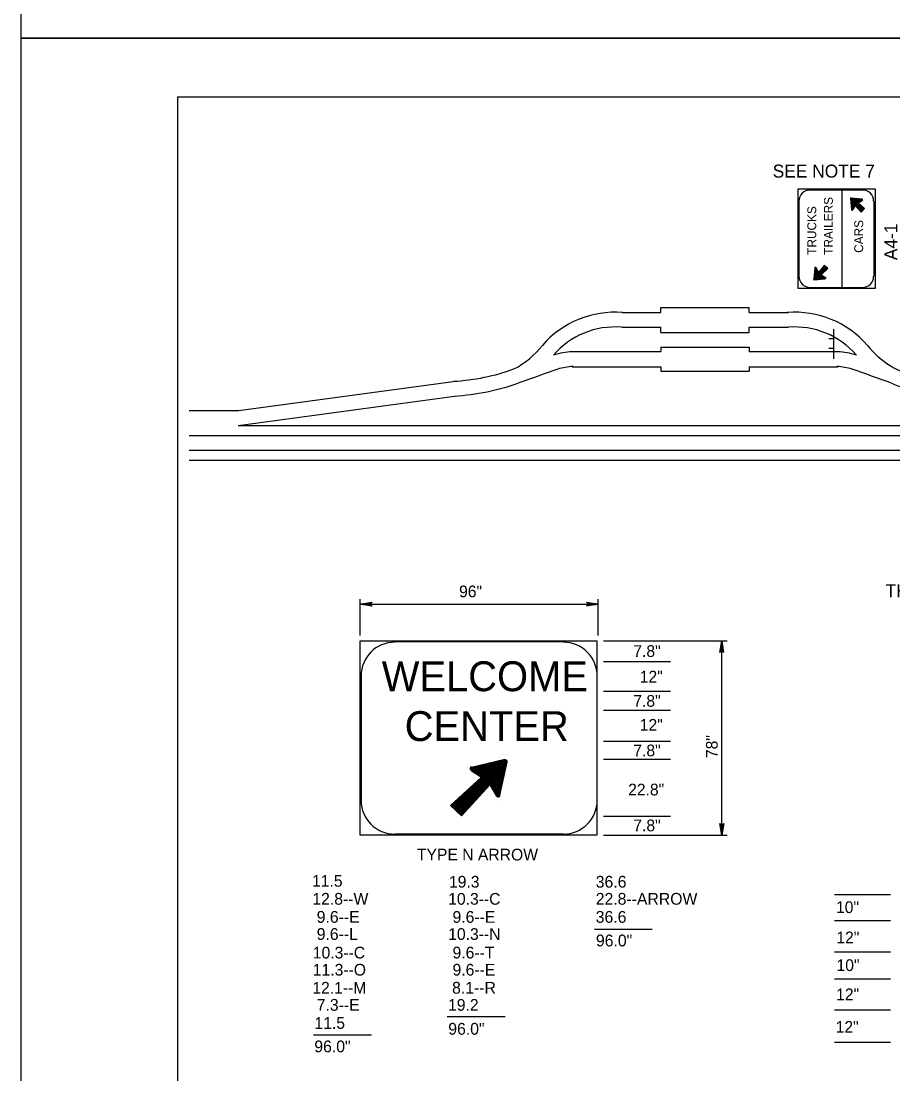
# Model space of a CAD drawing. Extents: x 2189973 to 2192941, y 2147557 to 2151454.
# Drawn here: x 2189973 to 2190705, y 2148636 to 2149520 of the extents above; entities that cross this region are included whole.
import ezdxf

# ---------------------------------------------------------------- set-up
doc = ezdxf.new("R2010")
doc.units = 0
doc.layers.add('Default', color=7, linetype='Continuous')
doc.layers.add('PLT-BNDY', color=7, linetype='Continuous')

# ---------------------------------------------------------------- blocks, each defined once
blk = doc.blocks.new('RARROW')
at = {"layer": 'Default'}
blk.add_lwpolyline([(-18.156, 2.28), (-17.479, 0.966), (0, 0), (-18.156, 2.28), (-19.086, 3.077), (0, 0), (-17.465, -0.864), (-18.103, -2.164), (0, 0), (-19.086, -3.033), (-18.103, -2.164)], dxfattribs=at)

msp = doc.modelspace()

# ---------------------------------------------------------------- linework, layer by layer
at = {"layer": 'Default'}
for p, q in [((2190104.48, 2149456.38), (2192683.21, 2149456.38)), ((2190104.48, 2149456.38), (2190104.48, 2147605.99)), ((2190635.15, 2149378.46), (2190679.45, 2149378.46)), ((2190662.22, 2149296.44), (2190662.22, 2149378.46)), ((2190669.19, 2149371.08), (2190670.01, 2149362.06)), ((2190679.04, 2149370.67), (2190669.6, 2149371.49)), ((2190669.6, 2149371.08), (2190669.6, 2149371.08)), ((2190675.76, 2149367.39), (2190679.04, 2149369.44)), ((2190679.04, 2149369.85), (2190679.04, 2149369.85)), ((2190679.86, 2149369.85), (2190679.86, 2149369.85)), ((2190679.86, 2149369.85), (2190679.86, 2149369.85)), ((2190670.42, 2149362.06), (2190670.42, 2149362.06)), ((2190670.42, 2149360.83), (2190670.42, 2149360.83)), ((2190670.42, 2149360.83), (2190670.42, 2149360.83)), ((2190673.29, 2149365.34), (2190671.24, 2149362.06)), ((2190673.29, 2149365.34), (2190673.29, 2149365.34)), ((2190673.29, 2149365.34), (2190678.22, 2149359.6)), ((2190674.52, 2149366.57), (2190674.52, 2149366.57)), ((2190675.76, 2149367.39), (2190675.76, 2149367.39)), ((2190681.09, 2149362.88), (2190675.76, 2149367.39)), ((2190678.22, 2149359.6), (2190681.09, 2149362.88)), ((2190681.09, 2149362.88), (2190681.09, 2149362.88)), ((2190678.22, 2149359.6), (2190678.22, 2149359.6)), ((2190639.26, 2149312.85), (2190638.44, 2149303.82)), ((2190640.08, 2149313.67), (2190640.08, 2149313.67)), ((2190640.08, 2149313.67), (2190640.08, 2149313.67)), ((2190640.08, 2149312.85), (2190640.08, 2149312.85)), ((2190642.54, 2149309.16), (2190640.49, 2149313.26)), ((2190647.05, 2149314.9), (2190642.54, 2149309.16)), ((2190642.54, 2149309.16), (2190642.54, 2149309.16)), ((2190643.36, 2149308.33), (2190643.36, 2149308.33)), ((2190644.59, 2149307.1), (2190650.33, 2149312.44)), ((2190644.59, 2149307.1), (2190644.59, 2149307.1)), ((2190644.59, 2149307.1), (2190647.87, 2149305.05)), ((2190647.05, 2149314.9), (2190647.05, 2149314.9)), ((2190650.33, 2149312.44), (2190647.05, 2149314.9)), ((2190650.33, 2149312.44), (2190650.33, 2149312.44)), ((2190638.44, 2149303.41), (2190638.44, 2149303.41)), ((2190638.44, 2149303.41), (2190638.44, 2149303.41)), ((2190638.85, 2149303.82), (2190638.85, 2149303.82)), ((2190638.85, 2149303), (2190647.87, 2149303.82)), ((2190647.87, 2149304.64), (2190647.87, 2149304.64)), ((2190648.69, 2149304.64), (2190648.69, 2149304.64)), ((2190648.69, 2149304.64), (2190648.69, 2149304.64)), ((2190633.92, 2149295.62), (2190627.77, 2149295.62)), ((2190635.15, 2149296.44), (2190679.45, 2149296.44)), ((2190663.86, 2149295.62), (2190659.35, 2149295.62)), ((2190477.26, 2149275.53), (2190510.07, 2149275.53)), ((2190510.07, 2149279.63), (2190584.3, 2149279.63)), ((2190510.07, 2149275.53), (2190510.07, 2149279.63)), ((2190584.3, 2149275.53), (2190584.3, 2149279.63)), ((2190584.3, 2149275.53), (2190617.11, 2149275.53)), ((2190477.26, 2149263.22), (2190510.07, 2149263.22)), ((2190510.07, 2149258.71), (2190510.07, 2149263.22)), ((2190584.3, 2149258.71), (2190584.3, 2149263.22)), ((2190584.3, 2149263.22), (2190617.11, 2149263.22)), ((2190510.07, 2149258.71), (2190584.3, 2149258.71)), ((2190655.25, 2149236.57), (2190655.25, 2149261.58)), ((2190510.07, 2149246.41), (2190584.3, 2149246.41)), ((2190510.07, 2149246.41), (2190510.07, 2149242.72)), ((2190584.3, 2149246.41), (2190584.3, 2149242.72)), ((2190655.25, 2149253.38), (2190651.15, 2149253.38)), ((2190655.25, 2149245.18), (2190651.15, 2149245.18)), ((2190435.84, 2149242.72), (2190510.07, 2149242.72)), ((2190584.3, 2149242.72), (2190658.53, 2149242.72)), ((2190435.84, 2149230.01), (2190510.07, 2149230.01)), ((2190510.07, 2149230.01), (2190510.07, 2149226.31)), ((2190584.3, 2149230.01), (2190584.3, 2149226.31)), ((2190584.3, 2149230.01), (2190658.53, 2149230.01)), ((2190510.07, 2149226.31), (2190584.3, 2149226.31)), ((2190153.69, 2149193.1), (2190335.78, 2149217.7)), ((2190155.33, 2149180.79), (2190337.01, 2149205.4)), ((2190337.01, 2149205.4), (2190337.01, 2149205.4)), ((2190337.01, 2149205.4), (2190337.01, 2149205.4)), ((2190155.33, 2149193.1), (2190114.32, 2149193.1)), ((2190155.33, 2149180.79), (2190939.04, 2149180.79)), ((2190155.33, 2149180.79), (2190155.33, 2149180.79)), ((2190155.33, 2149180.79), (2190155.33, 2149180.79)), ((2190114.32, 2149172.18), (2192679.93, 2149172.18)), ((2190114.32, 2149159.88), (2192679.93, 2149159.88)), ((2190114.32, 2149151.68), (2192679.93, 2149151.68)), ((2190257.86, 2149004.45), (2190257.86, 2149034.8)), ((2190457.58, 2149004.45), (2190457.58, 2149034.8)), ((2190257.86, 2149030.69), (2190457.58, 2149030.69)), ((2190462.09, 2148999.94), (2190565.73, 2148999.94)), ((2190561.21, 2148836.72), (2190561.21, 2148999.94)), ((2190462.09, 2148982.71), (2190518.12, 2148982.71)), ((2190258.68, 2148970.82), (2190258.68, 2148865.83)), ((2190456.76, 2148865.83), (2190456.76, 2148970.82)), ((2190462.09, 2148957.7), (2190518.12, 2148957.7)), ((2190462.09, 2148941.7), (2190518.12, 2148941.7)), ((2190462.09, 2148915.87), (2190518.12, 2148915.87)), ((2190379.25, 2148900.28), (2190351.36, 2148893.72)), ((2190381.3, 2148900.69), (2190381.3, 2148900.69)), ((2190462.09, 2148900.69), (2190518.12, 2148900.69)), ((2190348.08, 2148893.31), (2190348.08, 2148893.31)), ((2190375.15, 2148870.34), (2190380.89, 2148897.82)), ((2190359.56, 2148885.52), (2190333.73, 2148861.73)), ((2190350.95, 2148891.26), (2190359.56, 2148885.52)), ((2190359.56, 2148885.52), (2190359.56, 2148885.52)), ((2190342.75, 2148853.12), (2190366.54, 2148878.96)), ((2190366.54, 2148878.96), (2190366.54, 2148878.96)), ((2190366.54, 2148878.96), (2190372.28, 2148869.52)), ((2190374.33, 2148866.24), (2190374.33, 2148866.24)), ((2190333.73, 2148861.73), (2190342.75, 2148853.12)), ((2190462.09, 2148852.71), (2190518.12, 2148852.71)), ((2190462.09, 2148836.72), (2190565.73, 2148836.72)), ((2190702.84, 2148786.67), (2190655.73, 2148786.67)), ((2190702.84, 2148764.93), (2190655.73, 2148764.93)), ((2190454.45, 2148758.02), (2190502.75, 2148758.02)), ((2190702.84, 2148738.69), (2190655.73, 2148738.69)), ((2190702.84, 2148716.13), (2190655.73, 2148716.13)), ((2190702.84, 2148689.88), (2190655.73, 2148689.88)), ((2190330.71, 2148684.65), (2190379.54, 2148684.65)), ((2190218.72, 2148669.39), (2190267.19, 2148669.39)), ((2190702.84, 2148662.82), (2190655.73, 2148662.82))]:
    msp.add_line(p, q, dxfattribs=at)
for points in [[(2190625.31, 2149295.62), (2190625.31, 2149379.28), (2190631.05, 2149379.28), (2190638.44, 2149379.28), (2190643.77, 2149379.28), (2190651.56, 2149379.28), (2190656.89, 2149379.28), (2190663.04, 2149379.28), (2190675.34, 2149379.28), (2190690.11, 2149379.28), (2190690.11, 2149295.62), (2190672.47, 2149295.62), (2190665.5, 2149295.62), (2190656.89, 2149295.62), (2190647.46, 2149295.62), (2190635.15, 2149295.62), (2190625.31, 2149295.62)], [(2190626.13, 2149305.87), (2190626.13, 2149369.03)], [(2190669.19, 2149371.08), (2190670.42, 2149362.47), (2190670.42, 2149362.06), (2190670.83, 2149361.65), (2190670.83, 2149362.06), (2190673.29, 2149365.75), (2190673.29, 2149365.75), (2190678.22, 2149360.01), (2190680.68, 2149362.88), (2190675.34, 2149367.39), (2190675.34, 2149367.39), (2190679.04, 2149369.85), (2190679.45, 2149369.85), (2190679.04, 2149370.26), (2190679.04, 2149370.26), (2190669.6, 2149371.49), (2190669.6, 2149371.49), (2190669.19, 2149371.08), (2190669.6, 2149371.08), (2190670.42, 2149362.06), (2190672.88, 2149365.75), (2190678.22, 2149360.42), (2190680.68, 2149362.88), (2190674.93, 2149367.39), (2190679.04, 2149370.26), (2190669.6, 2149371.08), (2190670.42, 2149362.47), (2190672.88, 2149366.16), (2190678.22, 2149360.42), (2190680.27, 2149362.88), (2190674.93, 2149367.39), (2190679.04, 2149369.85), (2190669.6, 2149371.08), (2190670.83, 2149362.88), (2190672.88, 2149366.16), (2190678.22, 2149360.83), (2190679.86, 2149362.88), (2190674.93, 2149367.39), (2190678.63, 2149369.85), (2190670.01, 2149370.67), (2190670.83, 2149363.29), (2190672.88, 2149366.57), (2190678.22, 2149360.83), (2190679.86, 2149362.88), (2190674.52, 2149367.39), (2190678.22, 2149369.85), (2190670.01, 2149370.67), (2190670.83, 2149363.7), (2190672.88, 2149366.57), (2190678.22, 2149361.65), (2190679.45, 2149362.88), (2190674.52, 2149367.39), (2190677.4, 2149369.85), (2190670.42, 2149370.67), (2190671.24, 2149364.11), (2190672.88, 2149366.98), (2190678.22, 2149362.06), (2190679.45, 2149362.88), (2190674.11, 2149367.39), (2190677.4, 2149369.44), (2190670.42, 2149370.26), (2190671.24, 2149364.52), (2190672.88, 2149366.98), (2190678.22, 2149362.06), (2190679.04, 2149362.88), (2190674.11, 2149367.8), (2190676.58, 2149369.44), (2190670.42, 2149370.26), (2190671.24, 2149364.93), (2190672.88, 2149367.39), (2190678.22, 2149362.47), (2190679.04, 2149362.88), (2190674.11, 2149367.8), (2190676.17, 2149369.44), (2190670.83, 2149369.85), (2190671.24, 2149365.34), (2190672.88, 2149367.39), (2190678.22, 2149362.47), (2190678.63, 2149362.88), (2190673.29, 2149367.8), (2190675.76, 2149369.03), (2190671.24, 2149369.85), (2190671.65, 2149366.16), (2190672.88, 2149367.8), (2190678.22, 2149362.88), (2190678.63, 2149362.88), (2190673.29, 2149367.8), (2190675.34, 2149369.03), (2190671.24, 2149369.44), (2190671.65, 2149366.57), (2190672.88, 2149367.8), (2190678.22, 2149362.88), (2190672.88, 2149368.21), (2190674.93, 2149369.03), (2190671.24, 2149369.44), (2190671.65, 2149366.57), (2190672.88, 2149368.21), (2190675.76, 2149365.75), (2190672.88, 2149368.21), (2190674.93, 2149369.03), (2190671.65, 2149369.03)], [(2190671.65, 2149369.03), (2190671.65, 2149367.39), (2190674.52, 2149369.03), (2190671.65, 2149369.03), (2190672.06, 2149367.39), (2190674.11, 2149368.62), (2190672.06, 2149369.03), (2190672.06, 2149367.8), (2190673.29, 2149368.62), (2190672.06, 2149368.62), (2190672.06, 2149368.21), (2190672.88, 2149368.62), (2190672.06, 2149368.62), (2190672.06, 2149368.21), (2190672.47, 2149368.62)], [(2190688.88, 2149369.03), (2190688.88, 2149305.87)], [(2190638.85, 2149303.41), (2190647.46, 2149304.23), (2190647.87, 2149304.23), (2190648.28, 2149304.64), (2190647.87, 2149305.05), (2190644.18, 2149307.1), (2190644.18, 2149307.51), (2190649.92, 2149312.44), (2190647.05, 2149314.9), (2190642.54, 2149309.16), (2190642.54, 2149309.16), (2190640.08, 2149313.26), (2190640.08, 2149313.26), (2190639.67, 2149313.26), (2190639.67, 2149312.85), (2190638.44, 2149303.82), (2190638.44, 2149303.41), (2190638.85, 2149303.41), (2190638.85, 2149303.41), (2190647.87, 2149304.64), (2190644.18, 2149307.1), (2190649.51, 2149312.44), (2190647.05, 2149314.49), (2190642.54, 2149308.75), (2190639.67, 2149313.26), (2190638.85, 2149303.41), (2190647.46, 2149304.64), (2190643.77, 2149307.1), (2190649.51, 2149312.44), (2190647.05, 2149314.08), (2190642.54, 2149308.75), (2190640.08, 2149312.85), (2190638.85, 2149303.82), (2190647.05, 2149304.64), (2190643.77, 2149307.1), (2190648.69, 2149312.44), (2190647.05, 2149314.08), (2190642.54, 2149308.33), (2190640.08, 2149312.44), (2190639.26, 2149303.82), (2190646.64, 2149305.05), (2190643.36, 2149307.1), (2190648.69, 2149312.44), (2190647.05, 2149314.08), (2190642.54, 2149308.33), (2190640.08, 2149311.62), (2190639.26, 2149304.23), (2190646.23, 2149305.05), (2190643.36, 2149307.1), (2190648.28, 2149312.44), (2190647.05, 2149313.67), (2190642.54, 2149307.92), (2190640.08, 2149311.21), (2190639.26, 2149304.23), (2190645.82, 2149305.05), (2190642.95, 2149307.1), (2190647.87, 2149312.44), (2190647.05, 2149313.26), (2190642.54, 2149307.92), (2190640.49, 2149310.8), (2190639.67, 2149304.64), (2190645.41, 2149305.46), (2190642.95, 2149307.1), (2190647.87, 2149312.44), (2190647.05, 2149313.26), (2190642.13, 2149307.92), (2190640.49, 2149310.39), (2190639.67, 2149304.64), (2190645, 2149305.46), (2190642.54, 2149307.1), (2190647.46, 2149312.44), (2190647.05, 2149312.85), (2190642.13, 2149307.51), (2190640.49, 2149309.98), (2190640.08, 2149304.64), (2190644.18, 2149305.46), (2190642.54, 2149307.1), (2190647.46, 2149312.44), (2190647.05, 2149312.85), (2190642.13, 2149307.51), (2190640.9, 2149309.57), (2190640.08, 2149305.05), (2190643.77, 2149305.46), (2190642.13, 2149307.1), (2190647.05, 2149312.44), (2190647.05, 2149312.44), (2190642.13, 2149307.1), (2190640.9, 2149309.16), (2190640.49, 2149305.46), (2190643.36, 2149305.46), (2190642.13, 2149307.1), (2190647.05, 2149312.44), (2190641.72, 2149307.1), (2190640.9, 2149308.75), (2190640.49, 2149305.46), (2190643.36, 2149305.87), (2190641.72, 2149306.69), (2190644.18, 2149309.16), (2190641.72, 2149307.1), (2190640.9, 2149308.33), (2190640.9, 2149305.46)], [(2190640.9, 2149305.46), (2190642.54, 2149305.87), (2190640.9, 2149307.92), (2190640.9, 2149305.87), (2190642.54, 2149305.87), (2190641.31, 2149307.92), (2190640.9, 2149305.87), (2190642.13, 2149306.28), (2190641.31, 2149307.1), (2190641.31, 2149306.28), (2190641.72, 2149306.28), (2190641.31, 2149307.1), (2190641.31, 2149306.28), (2190641.72, 2149306.28), (2190641.31, 2149306.69)], [(2190428.46, 2148999.12), (2190286.98, 2148999.12)], [(2190334.14, 2148862.14), (2190360.8, 2148885.93), (2190350.95, 2148892.08), (2190350.54, 2148892.49), (2190351.36, 2148893.72), (2190379.66, 2148899.87), (2190380.89, 2148899.46), (2190380.89, 2148898.23), (2190374.74, 2148870.34), (2190373.92, 2148869.52), (2190372.69, 2148869.93), (2190366.54, 2148879.37), (2190342.75, 2148853.53), (2190334.96, 2148861.73), (2190361.21, 2148885.93), (2190350.95, 2148892.49), (2190350.95, 2148892.49), (2190351.36, 2148893.72), (2190379.66, 2148899.46), (2190380.07, 2148899.05), (2190380.48, 2148898.23), (2190374.33, 2148870.75), (2190373.51, 2148869.93), (2190372.69, 2148869.93), (2190366.54, 2148879.78), (2190342.34, 2148853.94), (2190335.37, 2148861.73), (2190361.62, 2148885.52), (2190351.36, 2148892.49), (2190351.36, 2148892.9), (2190351.36, 2148893.31), (2190380.07, 2148898.64), (2190373.51, 2148870.34), (2190366.54, 2148880.6), (2190342.34, 2148854.35), (2190336.19, 2148861.73), (2190361.62, 2148885.52), (2190351.36, 2148892.9), (2190379.66, 2148898.23)], [(2190351.77, 2148892.49), (2190379.66, 2148897.82), (2190373.51, 2148870.75), (2190366.54, 2148881.83), (2190341.93, 2148854.76), (2190336.6, 2148861.73), (2190362.03, 2148885.93), (2190353.41, 2148892.49), (2190378.84, 2148897.41), (2190373.1, 2148871.57), (2190366.95, 2148882.65), (2190341.93, 2148855.99), (2190337.83, 2148861.73), (2190362.85, 2148885.93), (2190355.05, 2148892.08), (2190378.02, 2148896.59), (2190372.69, 2148873.21), (2190366.95, 2148883.06), (2190341.93, 2148856.4), (2190338.65, 2148862.14), (2190363.26, 2148885.93), (2190356.69, 2148891.67), (2190377.61, 2148896.18), (2190372.28, 2148874.85), (2190366.95, 2148883.47), (2190342.34, 2148857.63), (2190339.47, 2148862.14), (2190364.08, 2148885.93), (2190357.92, 2148891.26), (2190376.79, 2148894.95), (2190372.28, 2148876.09), (2190366.95, 2148884.29), (2190342.34, 2148858.86), (2190340.7, 2148862.14), (2190364.49, 2148885.93), (2190359.15, 2148890.85), (2190375.97, 2148894.13), (2190371.87, 2148877.73), (2190366.95, 2148884.7), (2190342.75, 2148860.5), (2190342.34, 2148860.09), (2190341.11, 2148861.73), (2190365.31, 2148885.93), (2190360.8, 2148890.44), (2190375.15, 2148893.72), (2190371.05, 2148878.96), (2190366.95, 2148885.11), (2190342.34, 2148860.5), (2190341.52, 2148861.73), (2190366.13, 2148885.93), (2190362.03, 2148890.44), (2190373.92, 2148892.9), (2190371.05, 2148880.6), (2190366.95, 2148885.93), (2190341.93, 2148860.91), (2190341.93, 2148861.73), (2190366.54, 2148885.93), (2190362.85, 2148890.03), (2190373.51, 2148892.49), (2190371.05, 2148881.42), (2190364.08, 2148889.62), (2190372.69, 2148891.67), (2190370.64, 2148882.65), (2190365.31, 2148889.62), (2190371.87, 2148890.44), (2190370.23, 2148883.06), (2190366.13, 2148888.8), (2190371.05, 2148890.03), (2190370.23, 2148884.7), (2190367.36, 2148888.39), (2190370.64, 2148889.62), (2190369.82, 2148885.93), (2190368.59, 2148887.98), (2190369.82, 2148888.39), (2190369.41, 2148887.16)], [(2190286.98, 2148837.95), (2190428.46, 2148837.95)]]:
    msp.add_lwpolyline(points, dxfattribs=at)
msp.add_lwpolyline([(2190257.86, 2148836.72), (2190257.86, 2148999.94), (2190456.35, 2148999.94), (2190456.35, 2148836.72)], close=True, dxfattribs=at)
for centre, radius, start, end in [((2190635.27, 2149368.97), 9.28, 90, 180), ((2190679.42, 2149368.97), 9.28, 0, 90), ((2190669.74, 2149371.1), 0.58, 84.04981, 185.95018), ((2190678.83, 2149370.15), 0.58, 301.55392, 84.04981), ((2190670.68, 2149362), 0.58, 185.95019, 328.44608), ((2190639.76, 2149312.68), 0.58, 31.55393, 174.04981), ((2190635.27, 2149305.88), 9.28, 180, 270), ((2190638.81, 2149303.58), 0.58, 174.04981, 275.95018), ((2190647.91, 2149304.53), 0.58, 275.95019, 58.44608), ((2190679.42, 2149305.88), 9.28, 270, 0), ((2190471.58, 2149195.21), 80.51, 85.41339, 139.1043), ((2190622.69, 2149195.21), 80.51, 40.8957, 94.58661), ((2190471.58, 2149195.21), 68.14, 85.41339, 139.1043), ((2190622.69, 2149195.21), 68.14, 40.8957, 94.58661), ((2190354.97, 2149291), 70.46, 296.87931, 322.31094), ((2190739.3, 2149291), 70.46, 217.68906, 259.20477), ((2190439.28, 2149174.94), 67.66, 92.95256, 106.48658), ((2190654.99, 2149174.94), 67.66, 73.51342, 87.04744), ((2190325.5, 2149399.8), 182.36, 273.3346, 289.66361), ((2198936.79, 2125138.48), 25549.51, 109.463364, 109.540836), ((2190439.28, 2149174.94), 55.29, 92.95256, 106.48658), ((2190654.99, 2149174.94), 55.29, 73.51342, 87.04744), ((2182157.48, 2125138.48), 25549.51, 70.459164, 70.536636), ((2190325.5, 2149399.8), 194.73, 273.3346, 289.66361), ((2190739.3, 2149291), 82.83, 244.19575, 259.20477), ((2190286.87, 2148970.47), 28.33, 90, 180), ((2190428.37, 2148970.47), 28.33, 0, 90), ((2190351.55, 2148892.59), 1.57, 101.90425, 237.30801), ((2190351.55, 2148892.59), 1.57, 101.90425, 237.30804), ((2190379.6, 2148898.5), 1.57, 348.09575, 101.90426), ((2190379.6, 2148898.5), 1.57, 348.09575, 101.90425), ((2190286.87, 2148866.08), 28.33, 180, 270), ((2190373.69, 2148870.45), 1.57, 212.69199, 348.09575), ((2190373.69, 2148870.45), 1.57, 212.69196, 348.09575), ((2190428.37, 2148866.08), 28.33, 270, 0)]:
    msp.add_arc(centre, radius, start, end, dxfattribs=at)
at = {"layer": 'PLT-BNDY'}
for points in [[(2189973.25, 2151454.41), (2192732.43, 2151454.41), (2192732.43, 2149505.6), (2189973.25, 2149505.6)], [(2189973.25, 2149505.6), (2192732.43, 2149505.6), (2192732.43, 2147556.78), (2189973.25, 2147556.78)]]:
    msp.add_lwpolyline(points, close=True, dxfattribs=at)

# ---------------------------------------------------------------- block references
at = {"layer": 'Default', "xscale": 0.515679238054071, "yscale": 0.5369477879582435}
for p, rotation in [((2190257.86, 2149030.69), 180), ((2190561.21, 2148999.94), 89.99999999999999), ((2190561.21, 2148836.72), -90.00000000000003)]:
    msp.add_blockref('RARROW', p, dxfattribs=dict(at, rotation=rotation))
msp.add_blockref('RARROW', (2190457.58, 2149030.69), dxfattribs=at)

# ---------------------------------------------------------------- texts
at = {"layer": 'Default'}
for s, height, rotation, p in [('SEE NOTE 7', 10.883, 360, (2190603.99, 2149388.71)), ('TRAILERS', 7.419, 90, (2190654.43, 2149323.92)), ('TRUCKS', 7.419, 90, (2190640.49, 2149323.92)), ('CARS', 7.419, 90, (2190679.86, 2149325.56)), ('A4-1', 10.886, 90, (2190708.56, 2149319.41)), ('THEORETICAL GORE', 10.8833, 360, (2190698.72, 2149036.44)), ('WELCOME', 25.047, 360, (2190275.9, 2148957.7)), ('CENTER', 25.047, 360, (2190295.18, 2148915.86)), ('78"', 9.842, 90, (2190557.85, 2148901.53))]:
    msp.add_text(s, height=height, rotation=rotation, dxfattribs=at).set_placement(p)
for s, height, p in [('96"', 9.842, (2190340.81, 2149036.49)), ('7.8"', 9.842, (2190487.01, 2148986.42)), ('12"', 9.842, (2190492.44, 2148964.95)), ('7.8"', 9.842, (2190487.01, 2148944.59)), ('12"', 9.842, (2190492.44, 2148924.5)), ('7.8"', 9.842, (2190487.01, 2148903.02)), ('22.8"', 9.842, (2190482.66, 2148870.2)), ('7.8"', 9.842, (2190487.01, 2148840.14)), ('TYPE N ARROW', 9.8425, (2190305.43, 2148815.64)), ('11.5', 9.842, (2190217.43, 2148793.61)), ('19.3', 9.842, (2190332.34, 2148792.83)), ('36.6       ', 9.8942, (2190455.5, 2148792.83)), ('12.8--W', 9.894, (2190217.67, 2148778.48)), ('10.3--C', 9.842, (2190331.68, 2148778.48)), ('22.8--ARROW', 9.8942, (2190455.5, 2148778.48)), ('10"', 9.842, (2190657.11, 2148771.49)), (' 9.6--E', 9.894, (2190217.67, 2148763.31)), (' 9.6--E', 9.842, (2190331.68, 2148763.31)), ('36.6       ', 9.8942, (2190455.5, 2148763.31)), (' 9.6--L', 9.894, (2190217.67, 2148748.95)), ('10.3--N', 9.842, (2190331.68, 2148748.95)), ('96.0"        ', 9.8942, (2190455.66, 2148743.52)), ('12"', 9.842, (2190657.39, 2148746.09)), ('10.3--C', 9.842, (2190218.08, 2148733.37)), (' 9.6--T', 9.842, (2190331.68, 2148733.37)), ('10"', 9.842, (2190657.54, 2148722.83)), ('11.3--O', 9.842, (2190218.08, 2148719.01)), (' 9.6--E', 9.842, (2190331.68, 2148719.01)), ('12.1--M', 9.842, (2190217.67, 2148703.84)), (' 8.1--R', 9.894, (2190331.27, 2148703.84)), ('12"', 9.842, (2190657.23, 2148698.35)), (' 7.3--E', 9.894, (2190217.67, 2148689.49)), ('19.2', 9.842, (2190331.57, 2148689.49)), ('11.5  ', 9.842, (2190219.49, 2148674.31)), ('96.0"     ', 9.894, (2190331.74, 2148669.39)), ('12"', 9.842, (2190656.82, 2148671.02)), ('96.0"', 9.894, (2190219.34, 2148654.63))]:
    msp.add_text(s, height=height, dxfattribs=at).set_placement(p)

doc.saveas('drawing.dxf')
